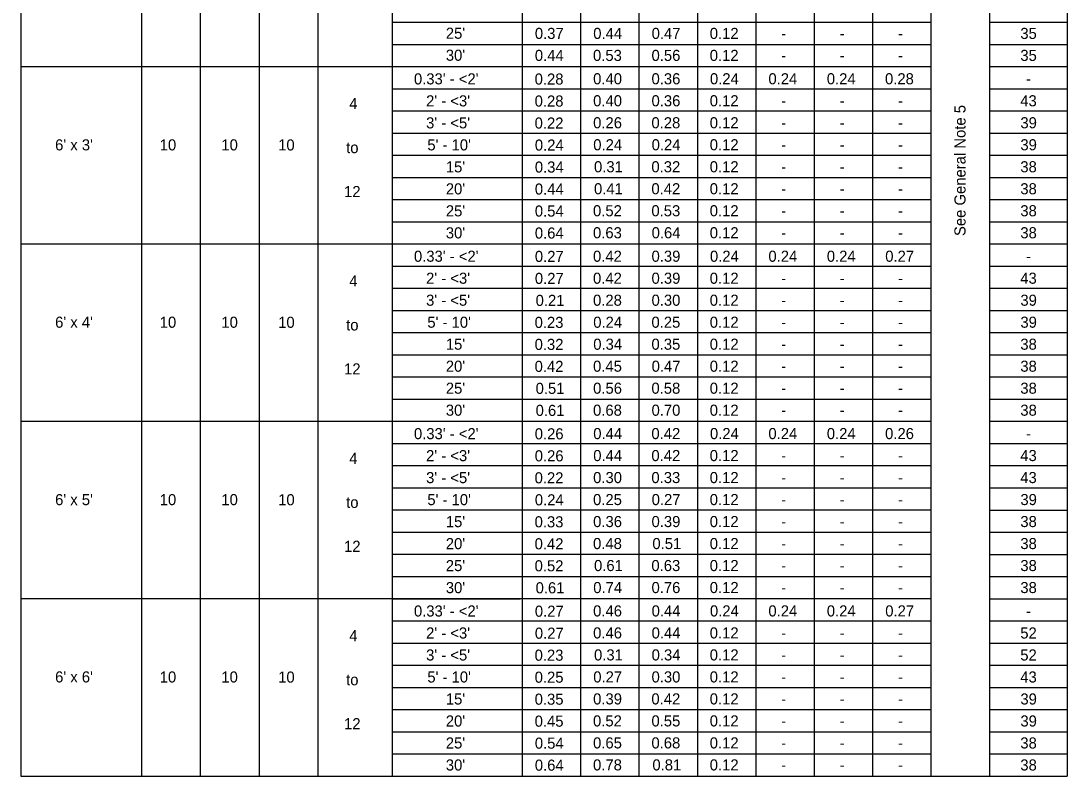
# Model space of a CAD drawing. Extents: x 10338.56 to 10340.78, y 76371.55 to 76372.62.
# Drawn here: x 10339.21 to 10339.805, y 76371.759 to 76372.188 of the extents above; entities that cross this region are included whole.
import ezdxf

# ---------------------------------------------------------------- set-up
doc = ezdxf.new("R2010")
doc.units = 0
doc.layers.add('AdhocPoint_dp', color=7, linetype='Continuous')
doc.layers.add('PlotBorder_dp', color=7, linetype='Continuous')

msp = doc.modelspace()

# ---------------------------------------------------------------- linework, layer by layer
at = {"layer": 'PlotBorder_dp'}
for p, q in [((10339.21023, 76372.53475), (10339.21023, 76371.75893)), ((10339.80497, 76372.53475), (10339.80497, 76371.75893)), ((10339.27886, 76372.51488), (10339.27886, 76371.75893)), ((10339.42131, 76372.51488), (10339.42131, 76371.75893)), ((10339.49519, 76372.51488), (10339.49519, 76371.75893)), ((10339.76078, 76372.51488), (10339.76078, 76371.75893)), ((10339.31222, 76372.50228), (10339.31222, 76371.75893)), ((10339.34558, 76372.50228), (10339.34558, 76371.75893)), ((10339.37895, 76372.50228), (10339.37895, 76371.75893)), ((10339.52839, 76372.47713), (10339.52839, 76371.75893)), ((10339.56158, 76372.47713), (10339.56158, 76371.75893)), ((10339.59478, 76372.47713), (10339.59478, 76371.75893)), ((10339.62798, 76372.47713), (10339.62798, 76371.75893)), ((10339.66118, 76372.47713), (10339.66118, 76371.75893)), ((10339.66118, 76372.47713), (10339.66118, 76371.75893)), ((10339.69438, 76372.47713), (10339.69438, 76371.75893)), ((10339.72758, 76372.47713), (10339.72758, 76371.75893)), ((10339.42131, 76372.18733), (10339.72758, 76372.18733)), ((10339.76078, 76372.18731), (10339.80497, 76372.18731)), ((10339.42131, 76372.17473), (10339.72758, 76372.17473)), ((10339.76078, 76372.17471), (10339.80497, 76372.17471)), ((10339.21023, 76372.16213), (10339.72758, 76372.16213)), ((10339.76078, 76372.16211), (10339.80497, 76372.16211)), ((10339.42131, 76372.14953), (10339.72758, 76372.14953)), ((10339.76078, 76372.14951), (10339.80497, 76372.14951)), ((10339.42131, 76372.13693), (10339.72758, 76372.13693)), ((10339.76078, 76372.13691), (10339.80497, 76372.13691)), ((10339.42131, 76372.12433), (10339.72758, 76372.12433)), ((10339.76078, 76372.12431), (10339.80497, 76372.12431)), ((10339.42131, 76372.11173), (10339.72758, 76372.11173)), ((10339.76078, 76372.11171), (10339.80497, 76372.11171)), ((10339.42131, 76372.09913), (10339.72758, 76372.09913)), ((10339.76078, 76372.09911), (10339.80497, 76372.09911)), ((10339.42131, 76372.08653), (10339.72758, 76372.08653)), ((10339.76078, 76372.08651), (10339.80497, 76372.08651)), ((10339.42131, 76372.07393), (10339.72758, 76372.07393)), ((10339.76078, 76372.07391), (10339.80497, 76372.07391)), ((10339.21023, 76372.06133), (10339.72758, 76372.06133)), ((10339.4219, 76372.06131), (10339.49407, 76372.06131)), ((10339.76078, 76372.06131), (10339.80497, 76372.06131)), ((10339.42131, 76372.04873), (10339.72758, 76372.04873)), ((10339.76078, 76372.04871), (10339.80497, 76372.04871)), ((10339.42131, 76372.03613), (10339.72758, 76372.03613)), ((10339.76078, 76372.03611), (10339.80497, 76372.03611)), ((10339.42131, 76372.02353), (10339.72758, 76372.02353)), ((10339.76078, 76372.02351), (10339.80497, 76372.02351)), ((10339.42131, 76372.01093), (10339.72758, 76372.01093)), ((10339.76078, 76372.01091), (10339.80497, 76372.01091)), ((10339.42131, 76371.99833), (10339.72758, 76371.99833)), ((10339.76078, 76371.99831), (10339.80497, 76371.99831)), ((10339.42131, 76371.98573), (10339.72758, 76371.98573)), ((10339.76078, 76371.98571), (10339.80497, 76371.98571)), ((10339.42131, 76371.97313), (10339.72758, 76371.97313)), ((10339.76078, 76371.97311), (10339.80497, 76371.97311)), ((10339.21023, 76371.96053), (10339.72758, 76371.96053)), ((10339.4219, 76371.96051), (10339.49407, 76371.96051)), ((10339.4219, 76371.96051), (10339.49407, 76371.96051)), ((10339.76078, 76371.96051), (10339.80497, 76371.96051)), ((10339.42131, 76371.94793), (10339.72758, 76371.94793)), ((10339.76078, 76371.94791), (10339.80497, 76371.94791)), ((10339.42131, 76371.93533), (10339.72758, 76371.93533)), ((10339.76078, 76371.93531), (10339.80497, 76371.93531)), ((10339.42131, 76371.92273), (10339.72758, 76371.92273)), ((10339.76078, 76371.92271), (10339.80497, 76371.92271)), ((10339.42131, 76371.91013), (10339.72758, 76371.91013)), ((10339.76078, 76371.91011), (10339.80497, 76371.91011)), ((10339.42131, 76371.89753), (10339.72758, 76371.89753)), ((10339.76078, 76371.89751), (10339.80497, 76371.89751)), ((10339.42131, 76371.88493), (10339.72758, 76371.88493)), ((10339.76078, 76371.88491), (10339.80497, 76371.88491)), ((10339.42131, 76371.87233), (10339.72758, 76371.87233)), ((10339.76078, 76371.87231), (10339.80497, 76371.87231)), ((10339.21023, 76371.85973), (10339.72758, 76371.85973)), ((10339.4219, 76371.85971), (10339.49407, 76371.85971)), ((10339.4219, 76371.85971), (10339.49407, 76371.85971)), ((10339.4219, 76371.85971), (10339.49407, 76371.85971)), ((10339.76078, 76371.85971), (10339.80497, 76371.85971)), ((10339.42131, 76371.84713), (10339.72758, 76371.84713)), ((10339.76078, 76371.84711), (10339.80497, 76371.84711)), ((10339.42131, 76371.83453), (10339.72758, 76371.83453)), ((10339.76078, 76371.83451), (10339.80497, 76371.83451)), ((10339.42131, 76371.82193), (10339.72758, 76371.82193)), ((10339.76078, 76371.82191), (10339.80497, 76371.82191)), ((10339.42131, 76371.80933), (10339.72758, 76371.80933)), ((10339.76078, 76371.80931), (10339.80497, 76371.80931)), ((10339.42131, 76371.79673), (10339.72758, 76371.79673)), ((10339.76078, 76371.79671), (10339.80497, 76371.79671)), ((10339.42131, 76371.78413), (10339.72758, 76371.78413)), ((10339.76078, 76371.78411), (10339.80497, 76371.78411)), ((10339.42131, 76371.77153), (10339.72758, 76371.77153)), ((10339.76078, 76371.77151), (10339.80497, 76371.77151)), ((10339.21023, 76371.75893), (10339.80497, 76371.75893)), ((10339.4219, 76371.75891), (10339.49407, 76371.75891))]:
    msp.add_line(p, q, dxfattribs=at)

# ---------------------------------------------------------------- texts
at = {"layer": 'AdhocPoint_dp'}
msp.add_text('See General Note 5', height=0.0063, rotation=90, dxfattribs=at).set_placement((10339.74723, 76372.0658))
for p in [(10339.28914, 76372.11446), (10339.32418, 76372.11446), (10339.35647, 76372.11441), (10339.28914, 76372.01368), (10339.32418, 76372.01368), (10339.35647, 76372.01363), (10339.28914, 76371.91285), (10339.32418, 76371.91285), (10339.35647, 76371.9128), (10339.28914, 76371.81207), (10339.32418, 76371.81207), (10339.35647, 76371.81201)]:
    msp.add_text('10', height=0.0063, dxfattribs=at).set_placement(p)
at = {"layer": 'PlotBorder_dp'}
for s, p in [("25'", (10339.45179, 76372.1779)), ('0.37', (10339.5024, 76372.1778)), ('0.44', (10339.53559, 76372.1778)), ('0.47', (10339.5688, 76372.1778)), ('0.12', (10339.60182, 76372.1778)), ('-', (10339.64245, 76372.1778)), ('-', (10339.67566, 76372.1778)), ('-', (10339.70885, 76372.1778)), ('35', (10339.77839, 76372.1778)), ("30'", (10339.45179, 76372.1654)), ('0.44', (10339.50239, 76372.1653)), ('0.53', (10339.53546, 76372.1653)), ('0.56', (10339.56873, 76372.1653)), ('0.12', (10339.60182, 76372.1653)), ('-', (10339.64245, 76372.1653)), ('-', (10339.67566, 76372.1653)), ('-', (10339.70885, 76372.1653)), ('35', (10339.77839, 76372.1653)), ("0.33' - <2'", (10339.43366, 76372.15196)), ('0.28', (10339.50228, 76372.15186)), ('0.40', (10339.53554, 76372.15202)), ('0.36', (10339.56873, 76372.15202)), ('0.24', (10339.60194, 76372.15202)), ('0.24', (10339.63518, 76372.15202)), ('0.24', (10339.66838, 76372.15202)), ('0.28', (10339.70146, 76372.15202)), ('-', (10339.7817, 76372.15202)), ('4', (10339.39689, 76372.13793)), ("2' - <3'", (10339.44056, 76372.13946)), ('0.28', (10339.50228, 76372.13936)), ('0.40', (10339.53554, 76372.13952)), ('0.36', (10339.56873, 76372.13952)), ('0.12', (10339.60182, 76372.13952)), ('43', (10339.77836, 76372.13952)), ('-', (10339.64245, 76372.13952)), ('-', (10339.67566, 76372.13952)), ('-', (10339.70885, 76372.13952)), ("3' - <5'", (10339.44056, 76372.12696)), ('0.22', (10339.50226, 76372.12686)), ('0.26', (10339.53553, 76372.12702)), ('0.28', (10339.56868, 76372.12702)), ('0.12', (10339.60182, 76372.12702)), ('39', (10339.77843, 76372.12702)), ('-', (10339.64245, 76372.12702)), ('-', (10339.67566, 76372.12702)), ('-', (10339.70885, 76372.12702)), ("6' x 3'", (10339.22966, 76372.11446)), ("5' - 10'", (10339.44128, 76372.11446)), ('0.24', (10339.50239, 76372.11436)), ('0.24', (10339.53559, 76372.11452)), ('0.24', (10339.56879, 76372.11452)), ('0.12', (10339.60182, 76372.11452)), ('39', (10339.77843, 76372.11452)), ('to', (10339.39511, 76372.11293)), ('-', (10339.64245, 76372.11452)), ('-', (10339.67566, 76372.11452)), ('-', (10339.70885, 76372.11452)), ("15'", (10339.45179, 76372.10196)), ('0.34', (10339.50239, 76372.10186)), ('0.31', (10339.53603, 76372.10202)), ('0.32', (10339.56866, 76372.10202)), ('0.12', (10339.60182, 76372.10202)), ('38', (10339.77839, 76372.10202)), ('-', (10339.64245, 76372.10202)), ('-', (10339.67566, 76372.10202)), ('-', (10339.70885, 76372.10202)), ('12', (10339.39393, 76372.08793)), ("20'", (10339.45179, 76372.08946)), ('0.44', (10339.50239, 76372.08936)), ('0.41', (10339.53603, 76372.08952)), ('0.42', (10339.56866, 76372.08952)), ('0.12', (10339.60182, 76372.08952)), ('-', (10339.64245, 76372.08952)), ('-', (10339.67566, 76372.08952)), ('-', (10339.70885, 76372.08952)), ('38', (10339.77839, 76372.08952)), ("25'", (10339.45179, 76372.07696)), ('0.54', (10339.50239, 76372.07686)), ('0.52', (10339.53546, 76372.07702)), ('0.53', (10339.56866, 76372.07702)), ('0.12', (10339.60182, 76372.07702)), ('-', (10339.64245, 76372.07702)), ('-', (10339.67566, 76372.07702)), ('-', (10339.70885, 76372.07702)), ('38', (10339.77839, 76372.07702)), ("30'", (10339.45179, 76372.06446)), ('0.64', (10339.50239, 76372.06436)), ('0.63', (10339.53546, 76372.06452)), ('0.64', (10339.56879, 76372.06452)), ('0.12', (10339.60182, 76372.06452)), ('-', (10339.64245, 76372.06452)), ('-', (10339.67566, 76372.06452)), ('-', (10339.70885, 76372.06452)), ('38', (10339.77839, 76372.06452)), ("0.33' - <2'", (10339.43366, 76372.05118)), ('0.27', (10339.5024, 76372.05108)), ('0.42', (10339.53546, 76372.05118)), ('0.39', (10339.56873, 76372.05118)), ('0.24', (10339.60194, 76372.05118)), ('0.24', (10339.63518, 76372.05118)), ('0.24', (10339.66838, 76372.05118)), ('0.27', (10339.70159, 76372.05118)), ('-', (10339.7817, 76372.05118)), ('4', (10339.39689, 76372.03713)), ("2' - <3'", (10339.44056, 76372.03868)), ('0.27', (10339.5024, 76372.03858)), ('0.42', (10339.53546, 76372.03868)), ('0.39', (10339.56873, 76372.03868)), ('0.12', (10339.60182, 76372.03868)), ('43', (10339.77836, 76372.03868)), ('-', (10339.64245, 76372.03868)), ('-', (10339.67566, 76372.03868)), ('-', (10339.70885, 76372.03868)), ("3' - <5'", (10339.44056, 76372.02618)), ('0.21', (10339.50283, 76372.02608)), ('0.28', (10339.53548, 76372.02618)), ('0.30', (10339.56874, 76372.02618)), ('0.12', (10339.60182, 76372.02618)), ('39', (10339.77843, 76372.02618)), ('-', (10339.64245, 76372.02618)), ('-', (10339.67566, 76372.02618)), ('-', (10339.70885, 76372.02618)), ("6' x 4'", (10339.22966, 76372.01368)), ("5' - 10'", (10339.44128, 76372.01368)), ('0.23', (10339.50226, 76372.01358)), ('0.24', (10339.53559, 76372.01368)), ('0.25', (10339.56869, 76372.01368)), ('0.12', (10339.60182, 76372.01368)), ('39', (10339.77843, 76372.01368)), ('to', (10339.39511, 76372.01213)), ('-', (10339.64245, 76372.01368)), ('-', (10339.67566, 76372.01368)), ('-', (10339.70885, 76372.01368)), ("15'", (10339.45179, 76372.00118)), ('0.32', (10339.50226, 76372.00108)), ('0.34', (10339.53559, 76372.00118)), ('0.35', (10339.56869, 76372.00118)), ('0.12', (10339.60182, 76372.00118)), ('38', (10339.77839, 76372.00118)), ('-', (10339.64245, 76372.00118)), ('-', (10339.67566, 76372.00118)), ('-', (10339.70885, 76372.00118)), ("20'", (10339.45179, 76371.98868)), ('0.42', (10339.50226, 76371.98858)), ('0.45', (10339.53549, 76371.98868)), ('0.47', (10339.5688, 76371.98868)), ('0.12', (10339.60182, 76371.98868)), ('38', (10339.77839, 76371.98868)), ('12', (10339.39393, 76371.98713)), ('-', (10339.64245, 76371.98868)), ('-', (10339.67566, 76371.98868)), ('-', (10339.70885, 76371.98868)), ("25'", (10339.45179, 76371.97618)), ('0.51', (10339.50283, 76371.97608)), ('0.56', (10339.53553, 76371.97618)), ('0.58', (10339.56868, 76371.97618)), ('0.12', (10339.60182, 76371.97618)), ('-', (10339.64245, 76371.97618)), ('-', (10339.67566, 76371.97618)), ('-', (10339.70885, 76371.97618)), ('38', (10339.77839, 76371.97618)), ("30'", (10339.45179, 76371.96368)), ('0.61', (10339.50283, 76371.96358)), ('0.68', (10339.53548, 76371.96368)), ('0.70', (10339.56874, 76371.96368)), ('0.12', (10339.60182, 76371.96368)), ('-', (10339.64245, 76371.96368)), ('-', (10339.67566, 76371.96368)), ('-', (10339.70885, 76371.96368)), ('38', (10339.77839, 76371.96368)), ("0.33' - <2'", (10339.43366, 76371.95035)), ('0.26', (10339.50233, 76371.95025)), ('0.44', (10339.53559, 76371.9504)), ('0.42', (10339.56866, 76371.9504)), ('0.24', (10339.60194, 76371.9504)), ('0.24', (10339.63518, 76371.9504)), ('0.24', (10339.66838, 76371.9504)), ('0.26', (10339.70151, 76371.9504)), ('-', (10339.7817, 76371.9504)), ('4', (10339.39689, 76371.93633)), ("2' - <3'", (10339.44056, 76371.93785)), ('0.26', (10339.50233, 76371.93775)), ('0.44', (10339.53559, 76371.9379)), ('0.42', (10339.56866, 76371.9379)), ('0.12', (10339.60182, 76371.9379)), ('43', (10339.77836, 76371.9379)), ('-', (10339.64245, 76371.9379)), ('-', (10339.67566, 76371.9379)), ('-', (10339.70885, 76371.9379)), ("3' - <5'", (10339.44056, 76371.92535)), ('0.22', (10339.50226, 76371.92525)), ('0.30', (10339.53554, 76371.9254)), ('0.33', (10339.56866, 76371.9254)), ('0.12', (10339.60182, 76371.9254)), ('43', (10339.77836, 76371.9254)), ('-', (10339.64245, 76371.9254)), ('-', (10339.67566, 76371.9254)), ('-', (10339.70885, 76371.9254)), ("6' x 5'", (10339.22966, 76371.91285)), ("5' - 10'", (10339.44128, 76371.91285)), ('0.24', (10339.50239, 76371.91275)), ('0.25', (10339.53549, 76371.9129)), ('0.27', (10339.5688, 76371.9129)), ('0.12', (10339.60182, 76371.9129)), ('39', (10339.77843, 76371.9129)), ('to', (10339.39511, 76371.91133)), ('-', (10339.64245, 76371.9129)), ('-', (10339.67566, 76371.9129)), ('-', (10339.70885, 76371.9129)), ("15'", (10339.45179, 76371.90035)), ('0.33', (10339.50226, 76371.90025)), ('0.36', (10339.53553, 76371.9004)), ('0.39', (10339.56873, 76371.9004)), ('0.12', (10339.60182, 76371.9004)), ('38', (10339.77839, 76371.9004)), ('-', (10339.64245, 76371.9004)), ('-', (10339.67566, 76371.9004)), ('-', (10339.70885, 76371.9004)), ("20'", (10339.45179, 76371.88785)), ('0.42', (10339.50226, 76371.88775)), ('0.48', (10339.53548, 76371.8879)), ('0.51', (10339.56923, 76371.8879)), ('0.12', (10339.60182, 76371.8879)), ('38', (10339.77839, 76371.8879)), ('12', (10339.39393, 76371.88633)), ('-', (10339.64245, 76371.8879)), ('-', (10339.67566, 76371.8879)), ('-', (10339.70885, 76371.8879)), ("25'", (10339.45179, 76371.87535)), ('0.52', (10339.50226, 76371.87525)), ('0.61', (10339.53603, 76371.8754)), ('0.63', (10339.56866, 76371.8754)), ('0.12', (10339.60182, 76371.8754)), ('-', (10339.64245, 76371.8754)), ('-', (10339.67566, 76371.8754)), ('-', (10339.70885, 76371.8754)), ('38', (10339.77839, 76371.8754)), ("30'", (10339.45179, 76371.86285)), ('0.61', (10339.50283, 76371.86275)), ('0.74', (10339.53559, 76371.8629)), ('0.76', (10339.56873, 76371.8629)), ('0.12', (10339.60182, 76371.8629)), ('-', (10339.64245, 76371.8629)), ('-', (10339.67566, 76371.8629)), ('-', (10339.70885, 76371.8629)), ('38', (10339.77839, 76371.8629)), ("0.33' - <2'", (10339.43366, 76371.84957)), ('0.27', (10339.5024, 76371.84946)), ('0.46', (10339.53553, 76371.84962)), ('0.44', (10339.56879, 76371.84962)), ('0.24', (10339.60194, 76371.84962)), ('0.24', (10339.63518, 76371.84962)), ('0.24', (10339.66838, 76371.84962)), ('0.27', (10339.70159, 76371.84962)), ('-', (10339.7817, 76371.84957)), ('4', (10339.39689, 76371.83553)), ("2' - <3'", (10339.44056, 76371.83707)), ('0.27', (10339.5024, 76371.83696)), ('0.46', (10339.53553, 76371.83712)), ('0.44', (10339.56879, 76371.83712)), ('0.12', (10339.60182, 76371.83712)), ('52', (10339.77837, 76371.83707)), ('-', (10339.64245, 76371.83712)), ('-', (10339.67566, 76371.83712)), ('-', (10339.70885, 76371.83712)), ("3' - <5'", (10339.44056, 76371.82457)), ('0.23', (10339.50226, 76371.82446)), ('0.31', (10339.53603, 76371.82462)), ('0.34', (10339.56879, 76371.82462)), ('0.12', (10339.60182, 76371.82462)), ('52', (10339.77837, 76371.82457)), ('-', (10339.64245, 76371.82462)), ('-', (10339.67566, 76371.82462)), ('-', (10339.70885, 76371.82462)), ("6' x 6'", (10339.22966, 76371.81212)), ("5' - 10'", (10339.44128, 76371.81207)), ('0.25', (10339.50229, 76371.81196)), ('0.27', (10339.5356, 76371.81212)), ('0.30', (10339.56874, 76371.81212)), ('0.12', (10339.60182, 76371.81212)), ('43', (10339.77836, 76371.81207)), ('to', (10339.39511, 76371.81053)), ('-', (10339.64245, 76371.81212)), ('-', (10339.67566, 76371.81212)), ('-', (10339.70885, 76371.81212)), ("15'", (10339.45179, 76371.79957)), ('0.35', (10339.50229, 76371.79946)), ('0.39', (10339.53553, 76371.79962)), ('0.42', (10339.56866, 76371.79962)), ('0.12', (10339.60182, 76371.79962)), ('39', (10339.77843, 76371.79957)), ('-', (10339.64245, 76371.79962)), ('-', (10339.67566, 76371.79962)), ('-', (10339.70885, 76371.79962)), ("20'", (10339.45179, 76371.78707)), ('0.45', (10339.50229, 76371.78696)), ('0.52', (10339.53546, 76371.78712)), ('0.55', (10339.56869, 76371.78712)), ('0.12', (10339.60182, 76371.78712)), ('39', (10339.77843, 76371.78707)), ('12', (10339.39393, 76371.78553)), ('-', (10339.64245, 76371.78712)), ('-', (10339.67566, 76371.78712)), ('-', (10339.70885, 76371.78712)), ("25'", (10339.45179, 76371.77457)), ('0.54', (10339.50239, 76371.77446)), ('0.65', (10339.53549, 76371.77462)), ('0.68', (10339.56868, 76371.77462)), ('0.12', (10339.60182, 76371.77462)), ('38', (10339.77839, 76371.77457)), ('-', (10339.64245, 76371.77462)), ('-', (10339.67566, 76371.77462)), ('-', (10339.70885, 76371.77462)), ("30'", (10339.45179, 76371.76207)), ('0.64', (10339.50239, 76371.76196)), ('0.78', (10339.53548, 76371.76212)), ('0.81', (10339.56923, 76371.76212)), ('0.12', (10339.60182, 76371.76212)), ('-', (10339.64245, 76371.76212)), ('-', (10339.67566, 76371.76212)), ('-', (10339.70885, 76371.76212)), ('38', (10339.77839, 76371.76207))]:
    msp.add_text(s, height=0.0063, dxfattribs=at).set_placement(p)

doc.saveas('drawing.dxf')
